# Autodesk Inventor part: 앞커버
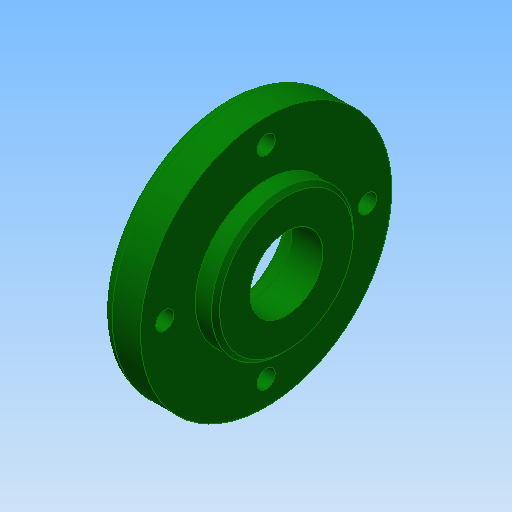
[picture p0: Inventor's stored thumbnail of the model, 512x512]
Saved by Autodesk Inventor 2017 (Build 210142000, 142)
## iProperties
Created: 2015-12
Part Number: 앞커버
Document SubType Name: Modeling
Designer: mdu
Density: 2.71 g/cm^3
Material: 알루미늄 6061
Appearance: 진녹색
Mass: 71.0233 g
Surface Area: 94.1932 cm^2
Volume: 26.2079 cm^3
Author: mdu
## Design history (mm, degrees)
sketch "스케치1"
  geometry: L1 (-7.5, 0)-(7.5, 0); L2 (-7.5, 0)-(-7.5, 31); L3 (-7.5, 31)-(2.5, 31); L4 (2.5, 31)-(2.5, 17.5); L5 (2.5, 17.5)-(7.5, 17.5); L6 (7.5, 17.5)-(7.5, 0); 2 further points
  constraints: 12 end point, 3 perpendicular, 1 coincident, 1 horizontal, 1 midpoint, 1 parallel
  dimensions: "d0" = 15 distance of L1.start L1.end; "d1" = 62 diameter of L3 L1; "d2" = 35 diameter of L5 L1; "d5" = 10 distance of L2.end L3.end
revolve "회전1" sketch "스케치1" stored, may be unused: angle "d6" = 90 deg
sketch "스케치2" dims "d42" = 50
  geometry: 3 further points
  constraints: 2 vertical alignment, 1 coincident, 2 other
hole "구멍1" sketch "스케치2" at (0, 25) diameter "d8" = 4.5; stored, may be unused: countersink angle "d12" = 90 deg, drill point angle "d14" = 118 deg; dims "d9" = 6, "d10" = 8, "d11" = 4.4, "d13" = 8
hole "구멍2" diameter "d20" = 18; stored, may be unused: countersink angle "d24" = 90 deg, drill point angle "d26" = 0 deg; dims "d18" = 10, "d19" = 10, "d21" = 6, "d22" = 8, "d23" = 4.4, "d25" = 8
hole "구멍3" diameter "d34" = 30; stored, may be unused: countersink angle "d38" = 90 deg, drill point angle "d40" = 0 deg; dims "d32" = 10, "d33" = 10, "d35" = 6, "d36" = 4, "d37" = 2, "d39" = 7.3
fillet "모깎기1" dims "d27" = 3, "d41" = 0.3
chamfer "모따기1" distance "d29" = 0.7; stored, may be unused: second distance "d30" = 2, angle "d31" = 30 deg
chamfer "모따기2" distance "d44" = 1; stored, may be unused: second distance "d45" = 2, angle "d46" = 45 deg
node "솔리드1"
pattern_circular "원형 패턴1" dims angle "d16" = 360 deg
